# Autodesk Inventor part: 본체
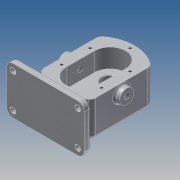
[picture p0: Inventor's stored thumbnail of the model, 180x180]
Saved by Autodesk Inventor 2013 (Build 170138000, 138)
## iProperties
Created: 2019-03
Part Number: 본체
Material: 알루미늄 6061
Document SubType Name: Modeling
Designer: Administrator
Density: 2.71 g/cm^3
Mass: 1191.56 g
Surface Area: 719.273 cm^2
Volume: 439.69 cm^3
Author: Administrator
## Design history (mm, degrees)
sketch "스케치1"
  geometry: L1 (-40, 44.721)-(-40, -44.721); L2 (40, 44.721)-(40, -44.721); A1 r 60 centre (0, 0) between (40, 44.721) and (-40, 44.721); A2 r 60 centre (0, 0) between (-40, -44.721) and (40, -44.721); 1 further point
  constraints: 4 end point, 4 point on circle, 2 centre point, 1 coincident, 1 vertical
  dimensions: "d1" = 80 distance between parallel lines of L2 L1; "d2" = 40 distance from line of point (0, 0) L2; "d3" = 60 radius of A1; "d4" = 60 radius of A2
extrude "돌출1" new body sketch "스케치1" distance "d5" = 53; taper "d6" = 0 deg
sketch "스케치2"
  geometry: L1 (24, 22)-(24, -22); L2 (-24, 22)-(-24, -22); A1 r 60 centre (0, 0) between (-40, -44.721) and (40, -44.721) reference; A2 r 24 centre (0, 22) between (24, 22) and (-24, 22); A3 r 24 centre (0, -22) between (-24, -22) and (24, -22)
  constraints: 4 end point, 4 point on circle, 2 centre point, 2 tangent, 1 vertical, 1 vertical alignment
  dimensions: "d7" = 48 diameter of A2; "d8" = 48 diameter of A3; "d9" = 44 distance of A3.centre A2.centre; "d10" = 22 distance of A2.centre A1.centre; "d11" = 48 distance between parallel lines of L2 L1
extrude "돌출2" cut sketch "스케치2" distance "d12" = 29; taper "d13" = 0 deg
sketch "스케치4"
  geometry: C1 r 19 at (0, 22); A1 r 60 centre (0, 0) between (40, 44.721) and (-40, 44.721) reference
  constraints: 1 centre point, 1 vertical alignment
  dimensions: "d15" = 38 diameter of C1; "d16" = 22 distance of A1.centre C1.centre
extrude "돌출3" join sketch "스케치4" distance "d17" = 17; taper "d18" = 0 deg
sketch "스케치5"
  geometry: C1 r 19 at (0, 0) reference; 1 further point
hole "구멍1" sketch "스케치5" at (0, 0) diameter "d19" = 17; stored, may be unused: countersink angle "d23" = 90 deg, drill point angle "d25" = 118 deg; dims "d20" = 6, "d21" = 28, "d22" = 7.3, "d24" = 8
sketch "스케치6"
  geometry: C1 r 8.5 at (0, 22) reference; C2 r 12.5 at (0, 22); C3 r 12.5 at (0, -22); A1 r 24 centre (0, 22) between (24, 22) and (-24, 22) reference; A2 r 24 centre (0, -22) between (-24, -22) and (24, -22) reference; 1 further point
  constraints: 2 centre point, 2 coincident
  dimensions: "d26" = 25 diameter of C2; "d27" = 25 diameter of C3
extrude "돌출4" cut sketch "스케치6" distance "d28" = 15; taper "d29" = 0 deg
node "작업 평면1"
sketch "스케치7"
  geometry: L1 (-60, 73)-(60, 73); L2 (60, 73)-(60, 0); L3 (60, 0)-(-60, 0); L4 (-60, 0)-(-60, 73); L5 (-60, 73)-(60, 0); L6 (60, 73)-(-60, 0); L7 (40, 0)-(-40, 0) reference; 2 further points
  constraints: 12 end point, 2 midpoint, 2 parallel, 1 collinear, 1 horizontal, 1 perpendicular
  dimensions: "d31" = 73 distance of L1.end L2.end; "d33" = 120 distance of L1.start L1.end; "d34" = 60 distance from line of point (0, 0) L2
extrude "돌출5" join sketch "스케치7" distance "d35" = 10; taper "d36" = 0 deg
fillet "모깎기1" dims "d37" = 10
fillet "모깎기2" dims "d38" = 3
sketch "스케치10"
  geometry: C1 r 4.5 at (-50, -10); C2 r 4.5 at (50, -10); C3 r 4.5 at (50, -63); C4 r 4.5 at (-50, -63); A1 r 7 centre (-50, -10) between (-50, -3) and (-57, -10) reference; A2 r 7 centre (-50, -63) between (-57, -63) and (-50, -70) reference; A3 r 7 centre (50, -63) between (50, -70) and (57, -63) reference; A4 r 7 centre (50, -10) between (57, -10) and (50, -3) reference; 1 further point
  constraints: 4 centre point, 4 coincident
  dimensions: "d39" = 9 diameter of C1; "d40" = 9 diameter of C2; "d41" = 9 diameter of C3; "d42" = 9 diameter of C4
extrude "돌출6" cut sketch "스케치10" stored distance "d43" = 10; taper "d44" = 0 deg
sketch "스케치12"
  geometry: L1 (50, 0)-(-50, 0) reference; L2 (-6, 0)-(6, 0); L3 (6, 0)-(6, -43); L4 (6, -43)-(-6, -43); L5 (-6, -43)-(-6, 0); 1 further point
  constraints: 8 end point, 2 parallel, 1 horizontal, 1 perpendicular, 1 point on line
  dimensions: "d51" = 43 distance between parallel lines of L1 L4; "d52" = 12 distance between parallel lines of L5 L3; "d53" = 6 distance from line of point (0, 0) L3
extrude "돌출8" join sketch "스케치12" stored distance "d54" = 10; taper "d55" = 0 deg
sketch "스케치13"
  geometry: L1 (-6, 3)-(6, 3) reference; L2 (-6, 3)-(-6, 0) reference; L3 (-6, 0)-(6, 0) reference; L4 (6, 0)-(6, 3) reference; 1 further point
extrude "돌출9" join sketch "스케치13" stored distance "d56" = 10; taper "d57" = 0 deg
sketch "스케치15"
  geometry: A1 r 24 centre (0, 22) between (24, 22) and (-24, 22) reference; A2 r 60 centre (0, 0) between (-40, -44.721) and (40, -44.721) reference; 1 further point
  constraints: 1 vertical alignment
  dimensions: "d68" = 53 distance of A2.centre point (0, 53)
hole "구멍3" sketch "스케치15" at (0, 53) diameter "d69" = 4.134; stored, may be unused: countersink angle "d73" = 90 deg, drill point angle "d75" = 118 deg; dims "d70" = 10, "d71" = 28, "d72" = 7.3, "d74" = 12
chamfer "모따기1" distance "d79" = 0.7; stored, may be unused: second distance "d80" = 2, angle "d81" = 30 deg
chamfer "모따기2" distance "d82" = 1; stored, may be unused: second distance "d83" = 2, angle "d84" = 30 deg
fillet "모깎기3" dims "d85" = 0.5
sketch "스케치17"
  geometry: L1 (-53, 0)-(-53, 89.443) reference; C1 r 11 at (-39, 44.721); 1 further point
  constraints: 1 centre point, 1 horizontal alignment
  dimensions: "d86" = 22 diameter of C1; "d88" = 14 distance from line of L1 C1.centre
extrude "돌출10" join sketch "스케치17" distance "d89" = 8; taper "d90" = 0 deg
sketch "스케치18"
  geometry: C1 r 11 at (0, 0) reference; 1 further point
hole "구멍4" sketch "스케치18" at (0, 0) diameter "d91" = 8.376; stored, may be unused: countersink angle "d95" = 90 deg, drill point angle "d97" = 118 deg; dims "d92" = 30, "d93" = 28, "d94" = 7.3, "d96" = 45
fillet "모깎기4" dims "d98" = 3
fillet "모깎기5" dims "d99" = 3
fillet "모깎기8" dims "d102" = 3
fillet "모깎기9" dims "d103" = 10
fillet "모깎기10" dims "d104" = 3
fillet "모깎기11" dims "d105" = 3
sketch "스케치19"
  geometry: L1 (-60, -10)-(-60, -63) reference; L2 (-50, -73)-(50, -73) reference; 2 further points
  constraints: 1 other
  dimensions: "d106" = 60 distance from line of L1 point (0, -63); "d107" = 10 distance from line of L2 point (0, -63)
feature "엠보싱1" sketch "스케치19" dims "d1" = 80, "d2" = 40, "d3" = 60, "d4" = 60, "d108" = 0.5, "d109" = 0
fillet "모깎기12" dims "d110" = 3
node "솔리드1"
pattern_circular "원형 패턴1" dims angle "d77" = 180 deg
mirror "대칭1"
mirror "대칭2"
other parameters: "d30" = -78
